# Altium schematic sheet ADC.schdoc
size 316 x 219 mm
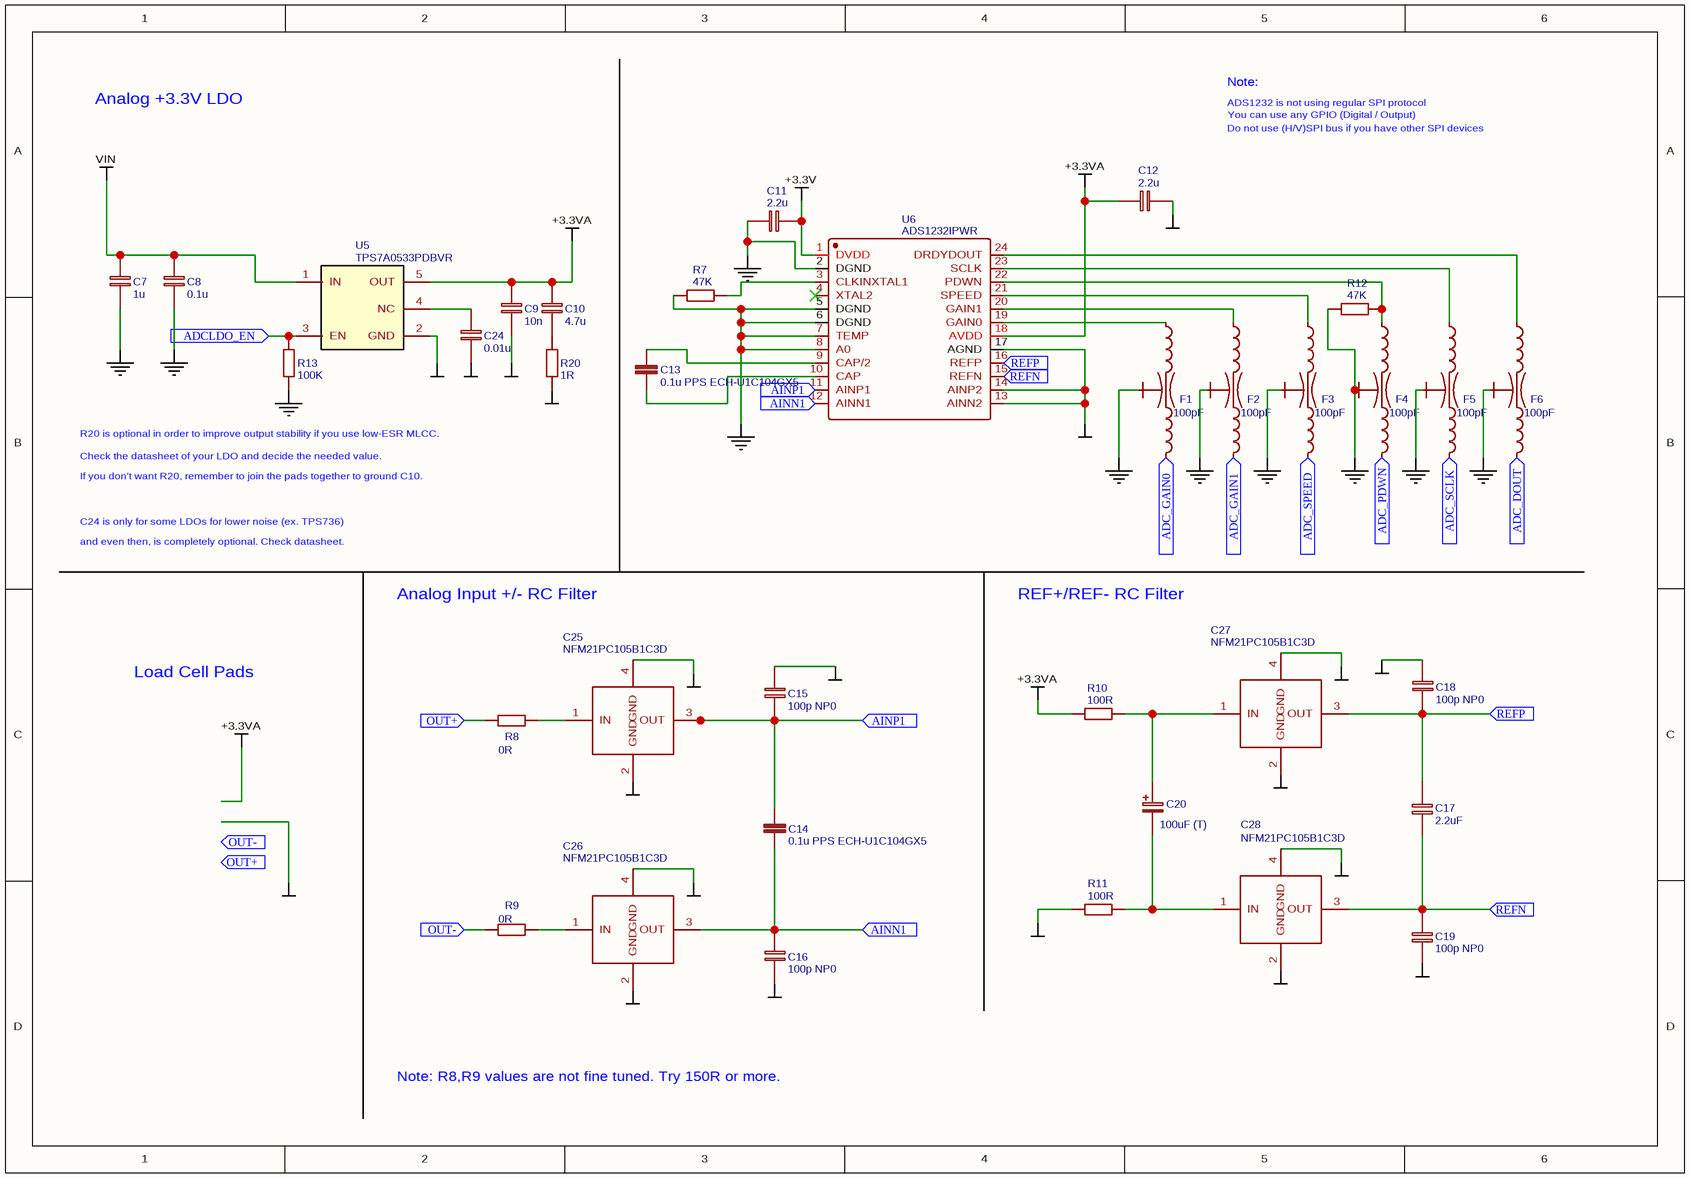
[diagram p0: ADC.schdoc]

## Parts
C7  1u  [0805]
C8  0.1u  [0805]
C9  10n  [0805]
C10  4.7u  [0805]
C11  2.2u  [0805]
C12  2.2u  [0805]
C13  0.1u PPS ECH-U1C104GX5  [1210]
C14  0.1u PPS ECH-U1C104GX5  [1210]
C15  100p NP0  [0805]
C16  100p NP0  [0805]
C17  2.2uF  [0805]
C18  100p NP0  [0805]
C19  100p NP0  [0805]
C20  100uF (T)  [CASE-C_6032]
C24  0.01u  [0805]
C25  NFM21PC105B1C3D  [NFM21-0805-4PIN]
C26  NFM21PC105B1C3D  [NFM21-0805-4PIN]
C27  NFM21PC105B1C3D  [NFM21-0805-4PIN]
C28  NFM21PC105B1C3D  [NFM21-0805-4PIN]
F1  100pF  [SMD-L-1.6MMX0.8MM]
F2  100pF  [SMD-L-1.6MMX0.8MM]
F3  100pF  [SMD-L-1.6MMX0.8MM]
F4  100pF  [SMD-L-1.6MMX0.8MM]
F5  100pF  [SMD-L-1.6MMX0.8MM]
F6  100pF  [SMD-L-1.6MMX0.8MM]
R7  47K  [0805]
R8  0R  [0805]
R9  0R  [0805]
R10  100R  [0805]
R11  100R  [0805]
R12  47K  [0805]
R13  100K  [0805]
R20  1R  [0805]
U5  TPS7A0533PDBVR  [SOT-23-5]
U6  ADS1232IPWR  [TSSOP-24]

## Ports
ADC_DOUT, ADC_GAIN0, ADC_GAIN1, ADC_PDWN, ADC_SCLK, ADC_SPEED, ADCLDO_EN, AINN1, AINP1, OUT+, OUT-, REFN, REFP

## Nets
+3.3V: C11.2 U6.1(DVDD)
+3.3VA: C9.1 C10.1 C12.1 U5.5(OUT) U6.18(AVDD)
GND: C7.2 C8.2 C9.2 C11.1 C12.2 C15.1 C16.2 C18.1 C19.1 C24.2 C25.2(GND) C25.4(GND) C26.2(GND) C26.4(GND) C27.2(GND) C27.4(GND) C28.2(GND) C28.4(GND) F1.2(GND) F2.2(GND) F3.2(GND) F4.2(GND) F5.2(GND) F6.2(GND) U5.2(GND) U6.2(DGND) U6.5(DGND) U6.6(DGND) U6.7(TEMP) U6.8(A0) U6.13(AINN2) U6.14(AINP2) U6.17(AGND)
VIN: C7.1 C8.1 U5.1(IN)
ADC_DOUT: F6.3(OUT) ; port ADC_DOUT
ADC_GAIN0: F1.3(OUT) ; port ADC_GAIN0
ADC_GAIN1: F2.3(OUT) ; port ADC_GAIN1
ADC_PDWN: F4.3(OUT) ; port ADC_PDWN
ADC_SCLK: F5.3(OUT) ; port ADC_SCLK
ADC_SPEED: F3.3(OUT) ; port ADC_SPEED
ADCLDO_EN: U5.3(EN) ; port ADCLDO_EN
AINN1: C14.1 C16.1 C26.3(OUT) U6.12(AINN1) ; port AINN1
AINP1: C14.2 C15.2 C25.3(OUT) U6.11(AINP1) ; port AINP1
REFN: C17.1 C19.2 C28.3(OUT) U6.15(REFN) ; port REFN
REFP: C17.2 C18.2 C27.3(OUT) U6.16(REFP) ; port REFP
NetC13_1: C13.1 U6.9(CAP/2)
NetC13_2: C13.2 U6.10(CAP)
NetC20_1: C20.1 C27.1(IN)
NetC20_2: C20.2 C28.1(IN)
NetC24_1: C24.1 U5.4(NC)
NetF1_1: F1.1(IN) U6.19(GAIN0)
NetF2_1: F2.1(IN) U6.20(GAIN1)
NetF3_1: F3.1(IN) U6.21(SPEED)
NetF4_1: F4.1(IN) U6.22(PDWN)
NetF5_1: F5.1(IN) U6.23(SCLK)
NetF6_1: F6.1(IN) U6.24(DRDYDOUT)

Not connected (* = marked no-connect by the designer): C10 2; C25 1(IN); C26 1(IN); R7 1 2; R8 1 2; R9 1 2; R10 1 2; R11 1 2; R12 1 2; R13 1 2; R20 1 2; U6 3(CLKINXTAL1) 4(XTAL2)*

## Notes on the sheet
- Analog +3.3V LDO
- ADS1232 is not using regular SPI protocol
- Note:
- You can use any GPIO (Digital / Output)
- Do not use (H/V)SPI bus if you have other SPI devices
- (near R13) R20 is optional in order to improve output stability if you use low-ESR MLCC.
- Check the datasheet of your LDO and decide the needed value.
- C24 is only for some LDOs for lower noise (ex. TPS736)
- If you don't want R20, remember to join the pads together to ground C10.
- and even then, is completely optional. Check datasheet.
- Analog Input +/- RC Filter
- REF+/REF- RC Filter
- Load Cell Pads
- Note: R8,R9 values are not fine tuned. Try 150R or more.
- Labels drawn without touching a wire or pin: GND

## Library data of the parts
C7 = 1u: nameAlias: Value(F)
C8 = 0.1u: nameAlias: Value(F)
C9 = 10n: nameAlias: Value(F)
C10 = 4.7u: nameAlias: Value(F)
C11 C12 = 2.2u: nameAlias: Value(F)
C13 C14 = 0.1u PPS ECH-U1C104GX5: description: Capacitor; Contributor: SparkFun
C15 C16 C18 C19 = 100p NP0: nameAlias: Value(F)
C17 = 2.2uF: nameAlias: Value(F)
C20 = 100uF (T): nameAlias: Value(F); Contributor: EasyEDA
C24 = 0.01u: nameAlias: Value(F)
C25-C28 = NFM21PC105B1C3D: BOM_Manufacturer: MuRata; nameAlias: Value(H); Value: 1.0μF(105); Contributor: John
F1-F6 = 100pF: BOM_Manufacturer: MuRata; BOM_Manufacturer Part: NFM18CC101R1C3D; nameAlias: Value; Contributor: LCSC
R7 R12 = 47K: nameAlias: Value(Ω)
R8 R9 = 0R: nameAlias: Value(Ω)
R10 R11 = 100R: nameAlias: Value(Ω)
R13 = 100K: nameAlias: Value(Ω)
R20 = 1R: nameAlias: Value(Ω)
U5 = TPS7A0533PDBVR: BOM_Manufacturer: TI; Contributor: blocked
U6 = ADS1232IPWR: BOM_Manufacturer: TI; Contributor: LCSC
